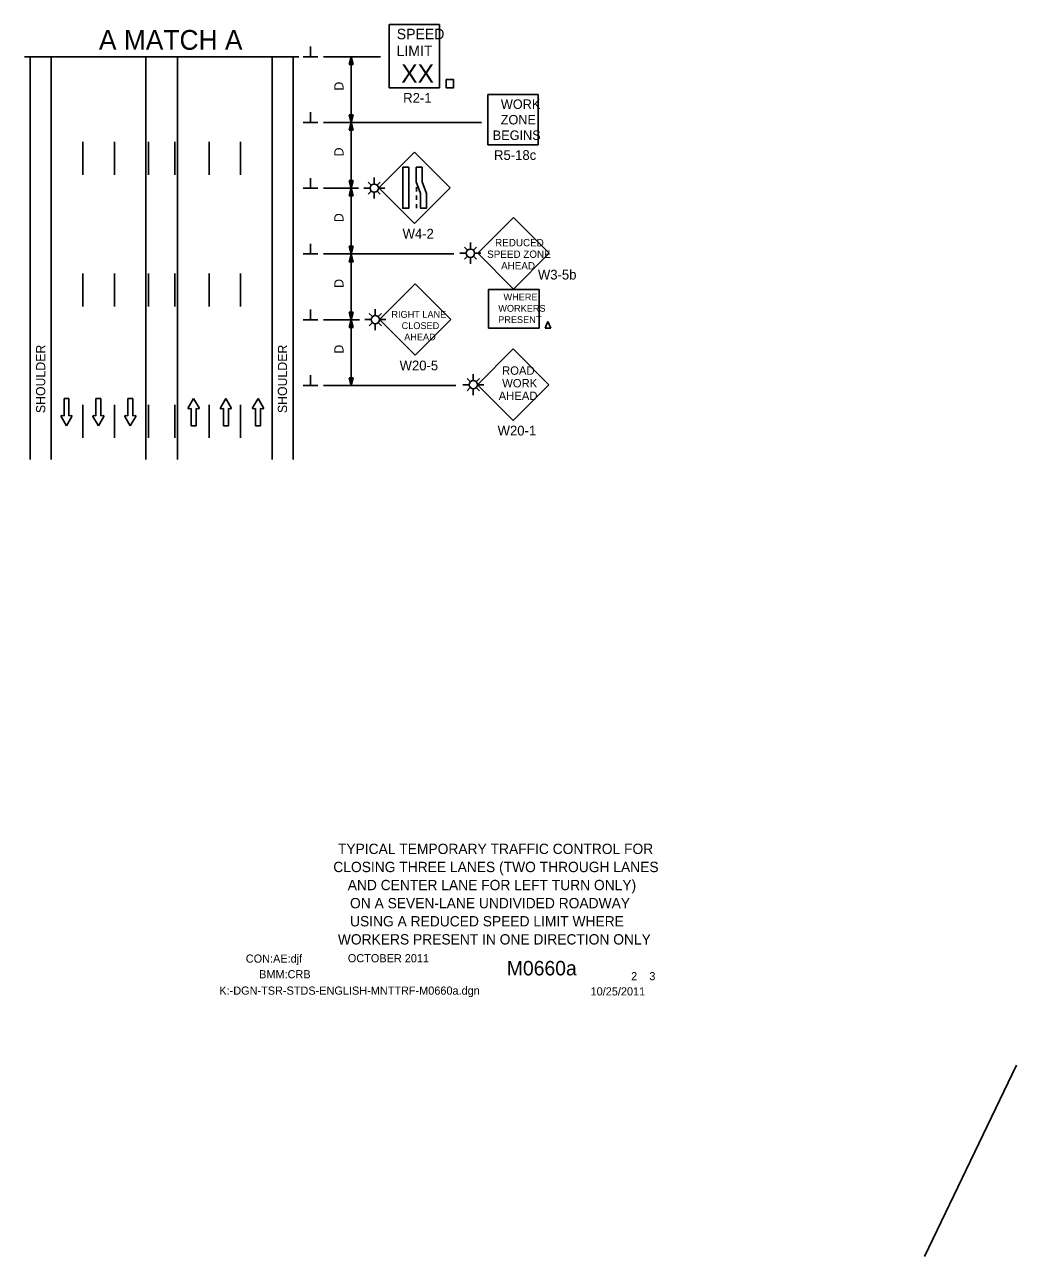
# Model space of a CAD drawing. Extents: x 16544 to 19504, y 5662 to 6922.
# Drawn here: x 17951 to 18706, y 5735 to 6671 of the extents above; entities that cross this region are included whole.
import ezdxf

# ---------------------------------------------------------------- set-up
doc = ezdxf.new("R2010")
doc.units = 0
for name, color, linetype in [('ALI_LEGAL_EX', 7, 'Continuous'), ('BORDER', 7, 'Continuous'), ('BORDER_SIGNAL_WO', 7, 'Continuous'), ('MT_SCRATCH_LEVEL_E', 7, 'Continuous'), ('PAVT_EDGE_EX', 7, 'Continuous'), ('TRAFFIC_SIGNS_PR', 7, 'Continuous'), ('TYPICAL_TEXT_DIMEN_PR', 7, 'Continuous')]:
    doc.layers.add(name, color=color, linetype=linetype)

msp = doc.modelspace()

# ---------------------------------------------------------------- linework, layer by layer
at = {"layer": 'ALI_LEGAL_EX'}
for points in [[(17995.77, 6582.18), (17995.77, 6557.18)], [(18019.77, 6582.18), (18019.77, 6557.18)], [(18045.77, 6582.18), (18045.77, 6557.18)], [(18065.77, 6582.18), (18065.77, 6557.18)], [(18091.77, 6582.18), (18091.77, 6557.18)], [(18115.77, 6582.18), (18115.77, 6557.18)], [(17995.77, 6482.18), (17995.77, 6457.18)], [(18019.77, 6482.18), (18019.77, 6457.18)], [(18045.77, 6482.18), (18045.77, 6457.18)], [(18065.77, 6482.18), (18065.77, 6457.18)], [(18091.77, 6482.18), (18091.77, 6457.18)], [(18115.77, 6482.18), (18115.77, 6457.18)], [(17995.77, 6382.18), (17995.77, 6357.18)], [(18019.77, 6382.18), (18019.77, 6357.18)], [(18045.77, 6382.18), (18045.77, 6357.18)], [(18065.77, 6382.18), (18065.77, 6357.18)], [(18091.77, 6382.18), (18091.77, 6357.18)], [(18115.77, 6382.18), (18115.77, 6357.18)]]:
    msp.add_lwpolyline(points, dxfattribs=at)
at = {"layer": 'BORDER'}
msp.add_line((18318.25, 6011.25), (18318.25, 6011.25), dxfattribs=at)
at = {"layer": 'MT_SCRATCH_LEVEL_E'}
for p, q in [((17985.18, 6387.14), (17981.44, 6387.14)), ((17981.44, 6387.14), (17981.44, 6373.88)), ((17985.18, 6387.14), (17981.44, 6387.14)), ((17981.44, 6387.14), (17981.44, 6373.88)), ((17985.18, 6373.88), (17985.18, 6387.14)), ((17985.18, 6373.88), (17985.18, 6387.14)), ((18009.44, 6387.14), (18005.69, 6387.14)), ((18005.69, 6387.14), (18005.69, 6373.88)), ((18009.44, 6387.14), (18005.69, 6387.14)), ((18005.69, 6387.14), (18005.69, 6373.88)), ((18009.44, 6373.88), (18009.44, 6387.14)), ((18009.44, 6373.88), (18009.44, 6387.14)), ((18033.69, 6387.14), (18029.95, 6387.14)), ((18029.95, 6387.14), (18029.95, 6373.88)), ((18033.69, 6387.14), (18029.95, 6387.14)), ((18029.95, 6387.14), (18029.95, 6373.88)), ((18033.69, 6373.88), (18033.69, 6387.14)), ((18033.69, 6373.88), (18033.69, 6387.14)), ((18080.01, 6387.14), (18075.9, 6379.9)), ((18080.01, 6387.14), (18075.9, 6379.9)), ((18076.38, 6379.22), (18078.16, 6379.53)), ((18076.38, 6379.22), (18078.16, 6379.53)), ((18078.16, 6379.53), (18078.16, 6366.27)), ((18078.16, 6379.53), (18078.16, 6366.27)), ((18084.16, 6379.9), (18080.01, 6387.14)), ((18084.16, 6379.9), (18080.01, 6387.14)), ((18081.9, 6366.27), (18081.9, 6379.53)), ((18081.9, 6379.53), (18083.68, 6379.22)), ((18081.9, 6366.27), (18081.9, 6379.53)), ((18081.9, 6379.53), (18083.68, 6379.22)), ((18104.51, 6387.14), (18100.4, 6379.9)), ((18104.51, 6387.14), (18100.4, 6379.9)), ((18100.88, 6379.22), (18102.65, 6379.53)), ((18100.88, 6379.22), (18102.65, 6379.53)), ((18102.65, 6379.53), (18102.65, 6366.27)), ((18102.65, 6379.53), (18102.65, 6366.27)), ((18108.65, 6379.9), (18104.51, 6387.14)), ((18108.65, 6379.9), (18104.51, 6387.14)), ((18106.4, 6366.27), (18106.4, 6379.53)), ((18106.4, 6379.53), (18108.17, 6379.22)), ((18106.4, 6366.27), (18106.4, 6379.53)), ((18106.4, 6379.53), (18108.17, 6379.22)), ((18129, 6387.14), (18124.89, 6379.9)), ((18129, 6387.14), (18124.89, 6379.9)), ((18125.37, 6379.22), (18127.15, 6379.53)), ((18125.37, 6379.22), (18127.15, 6379.53)), ((18127.15, 6379.53), (18127.15, 6366.27)), ((18127.15, 6379.53), (18127.15, 6366.27)), ((18133.15, 6379.9), (18129, 6387.14)), ((18133.15, 6379.9), (18129, 6387.14)), ((18130.89, 6366.27), (18130.89, 6379.53)), ((18130.89, 6379.53), (18132.67, 6379.22)), ((18130.89, 6366.27), (18130.89, 6379.53)), ((18130.89, 6379.53), (18132.67, 6379.22)), ((17979.18, 6373.51), (17983.33, 6366.27)), ((17979.18, 6373.51), (17983.33, 6366.27)), ((17981.44, 6373.88), (17979.66, 6374.2)), ((17981.44, 6373.88), (17979.66, 6374.2)), ((17983.33, 6366.27), (17987.44, 6373.51)), ((17983.33, 6366.27), (17987.44, 6373.51)), ((17986.96, 6374.2), (17985.18, 6373.88)), ((17986.96, 6374.2), (17985.18, 6373.88)), ((18003.44, 6373.51), (18007.58, 6366.27)), ((18003.44, 6373.51), (18007.58, 6366.27)), ((18005.69, 6373.88), (18003.92, 6374.2)), ((18005.69, 6373.88), (18003.92, 6374.2)), ((18007.58, 6366.27), (18011.69, 6373.51)), ((18007.58, 6366.27), (18011.69, 6373.51)), ((18011.21, 6374.2), (18009.44, 6373.88)), ((18011.21, 6374.2), (18009.44, 6373.88)), ((18027.69, 6373.51), (18031.84, 6366.27)), ((18027.69, 6373.51), (18031.84, 6366.27)), ((18029.95, 6373.88), (18028.17, 6374.2)), ((18029.95, 6373.88), (18028.17, 6374.2)), ((18031.84, 6366.27), (18035.95, 6373.51)), ((18031.84, 6366.27), (18035.95, 6373.51)), ((18035.47, 6374.2), (18033.69, 6373.88)), ((18035.47, 6374.2), (18033.69, 6373.88)), ((18078.16, 6366.27), (18081.9, 6366.27)), ((18078.16, 6366.27), (18081.9, 6366.27)), ((18102.65, 6366.27), (18106.4, 6366.27)), ((18102.65, 6366.27), (18106.4, 6366.27)), ((18127.15, 6366.27), (18130.89, 6366.27)), ((18127.15, 6366.27), (18130.89, 6366.27))]:
    msp.add_line(p, q, dxfattribs=at)
for centre, start, end in [((18076.31, 6379.67), 150.42484, 279.96381), ((18076.31, 6379.67), 150.42484, 279.96381), ((18083.75, 6379.67), 260.03619, 29.77312), ((18083.75, 6379.67), 260.03619, 29.77312), ((18100.8, 6379.67), 150.42484, 279.96381), ((18100.8, 6379.67), 150.42484, 279.96381), ((18108.24, 6379.67), 260.03619, 29.77312), ((18108.24, 6379.67), 260.03619, 29.77312), ((18125.3, 6379.67), 150.42484, 279.96381), ((18125.3, 6379.67), 150.42484, 279.96381), ((18132.74, 6379.67), 260.03619, 29.77312), ((18132.74, 6379.67), 260.03619, 29.77312), ((17979.59, 6373.74), 80.03619, 209.77312), ((17979.59, 6373.74), 80.03619, 209.77312), ((17987.03, 6373.74), 330.42484, 99.96381), ((17987.03, 6373.74), 330.42484, 99.96381), ((18003.85, 6373.74), 80.03619, 209.77312), ((18003.85, 6373.74), 80.03619, 209.77312), ((18011.29, 6373.74), 330.42484, 99.96381), ((18011.29, 6373.74), 330.42484, 99.96381), ((18028.1, 6373.74), 80.03619, 209.77312), ((18028.1, 6373.74), 80.03619, 209.77312), ((18035.54, 6373.74), 330.42484, 99.96381), ((18035.54, 6373.74), 330.42484, 99.96381)]:
    msp.add_arc(centre, 0.463, start, end, dxfattribs=at)
at = {"layer": 'PAVT_EDGE_EX'}
for p, q in [((17955.77, 6647.01), (17955.77, 6340.84)), ((17971.77, 6647.01), (17971.77, 6340.84)), ((18043.77, 6647.01), (18043.77, 6340.84)), ((18067.77, 6647.01), (18067.77, 6340.84)), ((18139.77, 6647.01), (18139.77, 6340.84)), ((18155.77, 6647.01), (18155.77, 6340.84))]:
    msp.add_line(p, q, dxfattribs=at)
at = {"layer": 'TRAFFIC_SIGNS_PR'}
for p, q in [((18228.72, 6671.43), (18267.12, 6671.43)), ((18228.72, 6623.43), (18228.72, 6671.43)), ((18267.12, 6623.43), (18267.12, 6671.43)), ((18228.72, 6623.43), (18267.12, 6623.43)), ((18303.68, 6579.96), (18303.68, 6618.36)), ((18303.68, 6618.36), (18342.08, 6618.36)), ((18342.08, 6579.96), (18342.08, 6618.36)), ((18303.68, 6579.96), (18342.08, 6579.96)), ((18247.98, 6574.44), (18220.82, 6547.29)), ((18275.13, 6547.29), (18247.98, 6574.44)), ((18214.84, 6549.58), (18212.73, 6551.69)), ((18217.35, 6550.62), (18217.35, 6555.12)), ((18219.86, 6549.58), (18221.97, 6551.69)), ((18249.62, 6547.78), (18249.62, 6544.58)), ((18214.2, 6547.06), (18209.36, 6547.06)), ((18214.84, 6544.55), (18212.73, 6542.44)), ((18217.35, 6539.1), (18217.35, 6543.51)), ((18219.86, 6544.55), (18221.97, 6542.44)), ((18220.5, 6547.06), (18225.39, 6547.06)), ((18220.82, 6547.29), (18247.98, 6520.14)), ((18247.98, 6520.14), (18275.13, 6547.29)), ((18249.62, 6541.38), (18249.62, 6538.18)), ((18249.62, 6534.98), (18249.62, 6531.78)), ((18323.23, 6524.68), (18296.08, 6497.53)), ((18350.38, 6497.53), (18323.23, 6524.68)), ((18288.01, 6500.09), (18285.91, 6502.2)), ((18290.53, 6501.13), (18290.53, 6505.63)), ((18293.04, 6500.09), (18295.15, 6502.2)), ((18287.37, 6497.58), (18282.54, 6497.58)), ((18288.01, 6495.06), (18285.91, 6492.95)), ((18290.53, 6489.61), (18290.53, 6494.02)), ((18293.04, 6495.06), (18295.15, 6492.96)), ((18293.68, 6497.58), (18298.56, 6497.58)), ((18296.08, 6497.53), (18323.23, 6470.37)), ((18323.23, 6470.37), (18350.38, 6497.53)), ((18248.5, 6474.24), (18221.35, 6447.09)), ((18275.65, 6447.09), (18248.5, 6474.24)), ((18304.35, 6470), (18342.75, 6470)), ((18304.35, 6440.68), (18304.35, 6470)), ((18342.75, 6440.68), (18342.75, 6470)), ((18218.19, 6450.65), (18218.19, 6455.15)), ((18215.04, 6447.09), (18210.2, 6447.09)), ((18215.68, 6449.61), (18213.57, 6451.71)), ((18220.71, 6449.61), (18222.82, 6451.71)), ((18221.35, 6447.09), (18226.23, 6447.09)), ((18221.35, 6447.09), (18248.5, 6419.94)), ((18248.5, 6419.94), (18275.65, 6447.09)), ((18215.68, 6444.58), (18213.57, 6442.47)), ((18218.19, 6439.13), (18218.19, 6443.54)), ((18220.71, 6444.58), (18222.81, 6442.47)), ((18304.35, 6440.68), (18342.75, 6440.68)), ((18323.05, 6424.79), (18295.86, 6397.61)), ((18350.24, 6397.61), (18323.05, 6424.79)), ((18290.2, 6400.12), (18288.09, 6402.23)), ((18292.71, 6401.16), (18292.71, 6405.66)), ((18295.22, 6400.12), (18297.33, 6402.23)), ((18289.55, 6397.61), (18284.72, 6397.61)), ((18290.19, 6395.1), (18288.09, 6392.99)), ((18292.71, 6389.64), (18292.71, 6394.05)), ((18295.22, 6395.1), (18297.33, 6392.99)), ((18295.86, 6397.61), (18300.74, 6397.61)), ((18295.86, 6397.61), (18323.05, 6370.42)), ((18323.05, 6370.42), (18350.24, 6397.61))]:
    msp.add_line(p, q, dxfattribs=at)
for points in [[(18272.13, 6623.43), (18277.73, 6623.43), (18277.73, 6629.6), (18272.13, 6629.6)], [(18239.08, 6563.03), (18239.08, 6531.78), (18243.57, 6531.78), (18243.57, 6563.03)], [(18249.22, 6563.03), (18249.22, 6551.84), (18252.56, 6542.96), (18252.56, 6531.78), (18257.05, 6531.78), (18257.05, 6542.96), (18253.71, 6551.84), (18253.71, 6563.03)]]:
    msp.add_lwpolyline(points, close=True, dxfattribs=at)
for points in [[(18349.5, 6445.62), (18347.27, 6440.68)], [(18347.27, 6440.68), (18349.5, 6445.62)], [(18351.74, 6440.68), (18349.5, 6445.62)], [(18349.5, 6445.62), (18351.74, 6440.68)], [(18347.27, 6440.68), (18351.74, 6440.68)], [(18351.74, 6440.68), (18347.27, 6440.68)]]:
    msp.add_lwpolyline(points, dxfattribs=at)
for centre in [(18217.35, 6547.06), (18290.53, 6497.58), (18218.19, 6447.09), (18292.71, 6397.61)]:
    msp.add_circle(centre, 3.15, dxfattribs=at)
at = {"layer": 'TYPICAL_TEXT_DIMEN_PR'}
for p, q in [((18168.89, 6647.01), (18168.89, 6654.79)), ((17951.47, 6647.01), (18160.07, 6647.01)), ((18043.77, 6647.01), (18067.77, 6647.01)), ((18174.52, 6647.01), (18163.27, 6647.01)), ((18178.77, 6647.01), (18222.17, 6647.01)), ((18198.2, 6641.15), (18199.77, 6647.01)), ((18199.77, 6647.01), (18201.34, 6641.15)), ((18199.77, 6647.01), (18199.77, 6597.01)), ((18199.77, 6641.15), (18198.2, 6641.15)), ((18201.34, 6641.15), (18199.77, 6641.15)), ((18168.89, 6597.01), (18168.89, 6604.79)), ((18174.52, 6597.01), (18163.27, 6597.01)), ((18178.77, 6597.01), (18298.96, 6597.01)), ((18199.77, 6597.01), (18198.2, 6602.87)), ((18198.2, 6602.87), (18199.77, 6602.87)), ((18198.2, 6591.15), (18199.77, 6597.01)), ((18199.77, 6602.87), (18201.34, 6602.87)), ((18201.34, 6602.87), (18199.77, 6597.01)), ((18199.77, 6597.01), (18201.34, 6591.15)), ((18199.77, 6597.01), (18199.77, 6547.01)), ((18199.77, 6591.15), (18198.2, 6591.15)), ((18201.34, 6591.15), (18199.77, 6591.15)), ((18168.89, 6547.01), (18168.89, 6554.79)), ((18199.77, 6547.01), (18198.2, 6552.87)), ((18198.2, 6552.87), (18199.77, 6552.87)), ((18199.77, 6552.87), (18201.34, 6552.87)), ((18201.34, 6552.87), (18199.77, 6547.01)), ((18174.52, 6547.01), (18163.27, 6547.01)), ((18205.29, 6547.01), (18178.77, 6547.01)), ((18198.2, 6541.15), (18199.77, 6547.01)), ((18199.77, 6541.15), (18198.2, 6541.15)), ((18199.77, 6547.01), (18201.34, 6541.15)), ((18199.77, 6547.01), (18199.77, 6497.01)), ((18201.34, 6541.15), (18199.77, 6541.15)), ((18168.89, 6497.01), (18168.89, 6504.79)), ((18199.77, 6497.01), (18198.2, 6502.87)), ((18198.2, 6502.87), (18199.77, 6502.87)), ((18199.77, 6502.87), (18201.34, 6502.87)), ((18201.34, 6502.87), (18199.77, 6497.01)), ((18174.52, 6497.01), (18163.27, 6497.01)), ((18178.77, 6497.01), (18277.86, 6497.01)), ((18198.2, 6491.15), (18199.77, 6497.01)), ((18199.77, 6497.01), (18201.34, 6491.15)), ((18199.77, 6497.01), (18199.77, 6447.01)), ((18199.77, 6491.15), (18198.2, 6491.15)), ((18201.34, 6491.15), (18199.77, 6491.15)), ((18168.89, 6447.01), (18168.89, 6454.79)), ((18174.52, 6447.01), (18163.27, 6447.01)), ((18206.13, 6447.01), (18178.77, 6447.01)), ((18199.77, 6447.01), (18198.2, 6452.87)), ((18198.2, 6452.87), (18199.77, 6452.87)), ((18198.2, 6441.15), (18199.77, 6447.01)), ((18199.77, 6452.87), (18201.34, 6452.87)), ((18201.34, 6452.87), (18199.77, 6447.01)), ((18199.77, 6447.01), (18201.34, 6441.15)), ((18199.77, 6447.01), (18199.77, 6397.01)), ((18199.77, 6441.15), (18198.2, 6441.15)), ((18201.34, 6441.15), (18199.77, 6441.15)), ((18168.89, 6397.01), (18168.89, 6404.79)), ((18199.77, 6397.01), (18198.2, 6402.87)), ((18198.2, 6402.87), (18199.77, 6402.87)), ((18199.77, 6402.87), (18201.34, 6402.87)), ((18201.34, 6402.87), (18199.77, 6397.01)), ((18174.52, 6397.01), (18163.27, 6397.01)), ((18178.77, 6397.01), (18279.55, 6397.01)), ((18705.75, 5880), (18635.9, 5734.7))]:
    msp.add_line(p, q, dxfattribs=at)

# ---------------------------------------------------------------- texts
at = {"layer": 'BORDER'}
for s, p in [('TYPICAL TEMPORARY TRAFFIC CONTROL FOR', (18189.75, 6040.69)), ('CLOSING THREE LANES (TWO THROUGH LANES', (18186.25, 6026.92)), ('AND CENTER LANE FOR LEFT TURN ONLY)', (18197.2, 6013.16)), ('ON A SEVEN-LANE UNDIVIDED ROADWAY ', (18198.95, 5999.4)), ('USING A REDUCED SPEED LIMIT WHERE ', (18198.95, 5985.63)), ('WORKERS PRESENT IN ONE DIRECTION ONLY', (18189.69, 5971.87))]:
    msp.add_text(s, height=7.8528, dxfattribs=at).set_placement(p)
at = {"layer": 'BORDER_SIGNAL_WO'}
for s, height, p in [('CON:AE:djf', 6.2, (18119.69, 5958.06)), ('    OCTOBER 2011    ', 6.2, (18188.08, 5958.34)), ('    M0660a   ', 11, (18301.86, 5948.38)), ('BMM:CRB   ', 6.2, (18129.81, 5946.17)), (' 2    3 ', 6.2, (18410.45, 5944.7)), ('K:-DGN-TSR-STDS-ENGLISH-MNTTRF-M0660a.dgn        ', 6.2, (18099.55, 5933.71)), ('10/25/2011    ', 6.2, (18381.93, 5933.13))]:
    msp.add_text(s, height=height, dxfattribs=at).set_placement(p)
at = {"layer": 'TRAFFIC_SIGNS_PR'}
for s, height, p in [('SPEED', 8, (18234.48, 6660.29)), ('LIMIT', 8, (18234.32, 6647.49)), ('XX', 14.031, (18237.83, 6627.19)), ('R2-1', 7.44, (18239.39, 6611.99)), ('WORK', 7.217, (18313.67, 6607.33)), ('ZONE', 7.217, (18313.56, 6595.52)), ('BEGINS', 7.217, (18307.48, 6583.71)), ('R5-18c', 7.44, (18308.49, 6568.52)), ('W4-2', 7.44, (18238.93, 6508.7)), ('REDUCED', 5.6, (18309.29, 6502.84)), ('SPEED ZONE', 5.6, (18303.28, 6494.04)), ('AHEAD', 5.6, (18313.84, 6485.24)), ('W3-5b', 7.44, (18341.87, 6477.59)), ('WHERE', 5.2, (18315.67, 6461.68)), ('WORKERS', 5.2, (18311.74, 6453.08)), ('RIGHT LANE', 5.2, (18230.42, 6448.49)), ('CLOSED', 5.2, (18238.21, 6439.89)), ('PRESENT', 5.2, (18311.67, 6444.48)), ('AHEAD', 5.2, (18240.16, 6431.29)), ('W20-5', 7.44, (18236.67, 6408.5)), ('ROAD', 6.408, (18314.58, 6405.15)), ('WORK', 6.408, (18314.69, 6395.54)), ('AHEAD', 6.408, (18312, 6385.93)), ('W20-1', 7.449, (18311.2, 6358.97))]:
    msp.add_text(s, height=height, dxfattribs=at).set_placement(p)
at = {"layer": 'TYPICAL_TEXT_DIMEN_PR'}
msp.add_text('A MATCH A', height=15, dxfattribs=at).set_placement((18007.97, 6652.33))
for s, p in [('D', (18193.99, 6621.23)), ('D', (18193.99, 6571.23)), ('D', (18193.99, 6521.23)), ('D', (18193.99, 6471.23)), ('SHOULDER', (17967.14, 6375.99)), ('SHOULDER', (18151.05, 6375.99)), ('D', (18193.99, 6421.23))]:
    msp.add_text(s, height=7, rotation=90, dxfattribs=at).set_placement(p)

doc.saveas('drawing.dxf')
